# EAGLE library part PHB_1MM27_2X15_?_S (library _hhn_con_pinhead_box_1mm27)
Pin Header Box-Type, 1.27mm/0.5"/50mil Pitch, 2x15 Circuits, single gates in schematic Note: see library description for an important note about THT-version
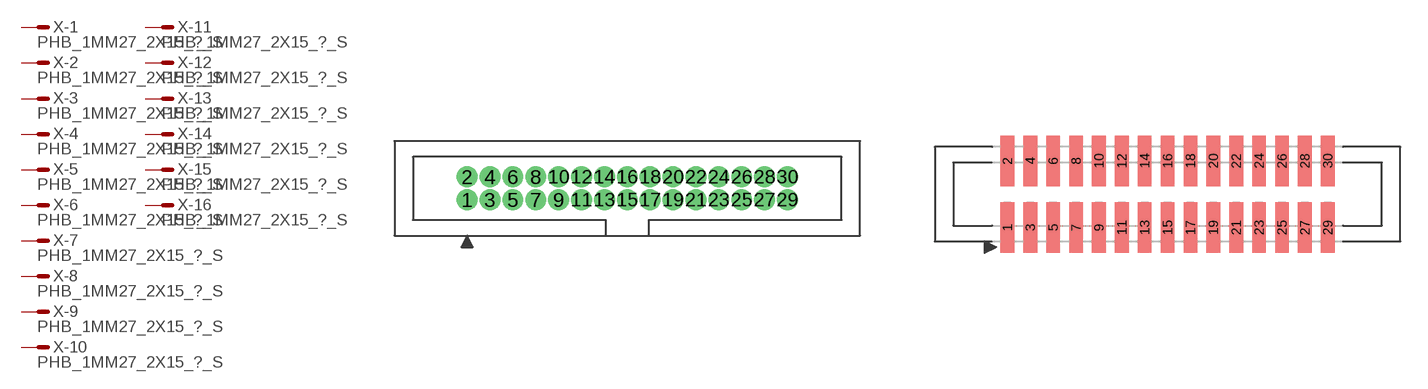
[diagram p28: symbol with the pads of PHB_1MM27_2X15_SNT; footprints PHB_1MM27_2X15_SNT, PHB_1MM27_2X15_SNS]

Designator prefix X; gates -1=M -2=M -3=M -4=M -5=M -6=M -7=M -8=M -9=M -10=M -11=M -12=M -13=M -14=M -15=M -16=M -17=M -18=M -19=M -20=M -21=M -22=M -23=M -24=M -25=M -26=M -27=M -28=M -29=M -30=M

## PHB_1MM27_2X15_SNT_S  [PHB_1MM27_2X15_SNT]
1  -1:S  pas
2  -2:S  pas
3  -3:S  pas
4  -4:S  pas
5  -5:S  pas
6  -6:S  pas
7  -7:S  pas
8  -8:S  pas
9  -9:S  pas
10  -10:S  pas
11  -11:S  pas
12  -12:S  pas
13  -13:S  pas
14  -14:S  pas
15  -15:S  pas
16  -16:S  pas
17  -17:S  pas
18  -18:S  pas
19  -19:S  pas
20  -20:S  pas
21  -21:S  pas
22  -22:S  pas
23  -23:S  pas
24  -24:S  pas
25  -25:S  pas
26  -26:S  pas
27  -27:S  pas
28  -28:S  pas
29  -29:S  pas
30  -30:S  pas

## PHB_1MM27_2X15_SNS_S  [PHB_1MM27_2X15_SNS]
Pads as for PHB_1MM27_2X15_SNT

## Footprint PHB_1MM27_2X15_SNT (pad centres in mm)
Pin Header Box-Type, 1.27mm Pitch, 2x15 circuits, Straight, No Locking, THT Important Note: Diameter in this lbr is set to a specific value (NOT 'auto' = 0), this is ignored by actual eagle versions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
drill 0.65 pad 1 round: 1 -8.89,-0.635; 2 -8.89,0.635; 3 -7.62,-0.635; 4 -7.62,0.635; 5 -6.35,-0.635; 6 -6.35,0.635; 7 -5.08,-0.635; 8 -5.08,0.635; 9 -3.81,-0.635; 10 -3.81,0.635; 11 -2.54,-0.635; 12 -2.54,0.635; 13 -1.27,-0.635; 14 -1.27,0.635; 15 0,-0.635; 16 0,0.635; 17 1.27,-0.635; 18 1.27,0.635; 19 2.54,-0.635; 20 2.54,0.635; 21 3.81,-0.635; 22 3.81,0.635; 23 5.08,-0.635; 24 5.08,0.635; 25 6.35,-0.635; 26 6.35,0.635; 27 7.62,-0.635; 28 7.62,0.635; 29 8.89,-0.635; 30 8.89,0.635

## Footprint PHB_1MM27_2X15_SNS (pad centres in mm)
Pin Header Box-Type, 1.27mm Pitch, 2x15 circuits, Straight, No Locking, SMT
smd 0.76 x 2.8: 1 -8.89,-1.85; 2 -8.89,1.85; 3 -7.62,-1.85; 4 -7.62,1.85; 5 -6.35,-1.85; 6 -6.35,1.85; 7 -5.08,-1.85; 8 -5.08,1.85; 9 -3.81,-1.85; 10 -3.81,1.85; 11 -2.54,-1.85; 12 -2.54,1.85; 13 -1.27,-1.85; 14 -1.27,1.85; 15 0,-1.85; 16 0,1.85; 17 1.27,-1.85; 18 1.27,1.85; 19 2.54,-1.85; 20 2.54,1.85; 21 3.81,-1.85; 22 3.81,1.85; 23 5.08,-1.85; 24 5.08,1.85; 25 6.35,-1.85; 26 6.35,1.85; 27 7.62,-1.85; 28 7.62,1.85; 29 8.89,-1.85; 30 8.89,1.85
